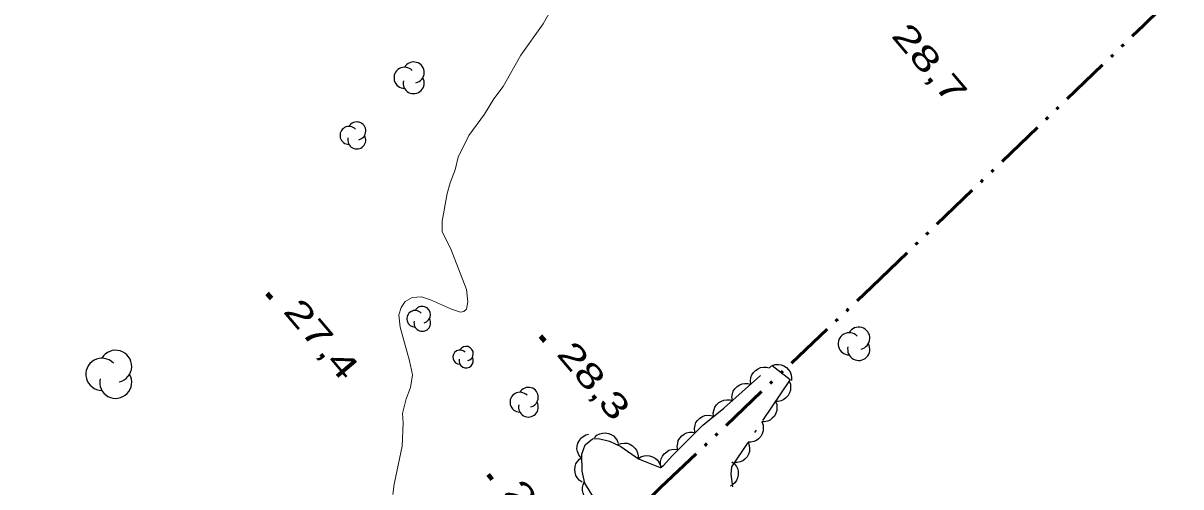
# Model space of a CAD drawing. Extents: x 386081 to 389416, y 5130568 to 5134082.
# Drawn here: x 388446.7 to 388588.2, y 5131862.1 to 5131918.7 of the extents above; entities that cross this region are included whole.
import ezdxf

# ---------------------------------------------------------------- set-up
doc = ezdxf.new("R2010")
doc.units = 0
doc.header["$LTSCALE"] = 1.2
doc.linetypes.add('DASH_DOUBLE_DOT', pattern=[9.2, 5, -1.2, 0.3, -1.2, 0.3, -1.2])
doc.linetypes.add('DOT_DASHED', pattern=[7.7, 5, -1.2, 0.3, -1.2])
for name, color, linetype, lineweight in [('2', 7, 'Continuous', 13), ('3', 7, 'Continuous', 140), ('4', 7, 'DASH_DOUBLE_DOT', 53), ('44', 7, 'Continuous', 25)]:
    doc.layers.add(name, color=color, linetype=linetype, lineweight=lineweight)

msp = doc.modelspace()

# ---------------------------------------------------------------- linework, layer by layer
at = {"layer": '2'}
msp.add_lwpolyline([(388491.9, 5131861.11), (388492.06, 5131862.38), (388493.02, 5131867.01), (388493.16, 5131869.86), (388493.06, 5131871), (388493.5, 5131872.79), (388494.05, 5131874.18), (388494.29, 5131875.74), (388493.93, 5131877.43), (388492.79, 5131881.57), (388492.61, 5131883.08), (388492.91, 5131883.98), (388493.4, 5131884.7), (388494.24, 5131885.19), (388495.39, 5131885.25), (388496.47, 5131884.89), (388499.06, 5131883.75), (388500.15, 5131883.4), (388500.57, 5131883.46), (388500.87, 5131883.76), (388501.05, 5131884.66), (388500.87, 5131886.17), (388498.95, 5131891.21), (388497.93, 5131893.2), (388497.93, 5131894.52), (388498.53, 5131897.89), (388498.9, 5131899.21), (388499.5, 5131900.78), (388499.87, 5131902.35), (388501.19, 5131904.99), (388503.07, 5131907.59), (388504.21, 5131909.45), (388505.36, 5131910.96), (388507.54, 5131914.81), (388510.25, 5131918.61), (388511.7, 5131921.14)], dxfattribs=at)
at = {"layer": '3'}
for p, q in [((388476.55, 5131885.68), (388477.06, 5131885.07)), ((388509.95, 5131880.45), (388510.46, 5131879.84)), ((388503.53, 5131863.57), (388504.04, 5131862.96))]:
    msp.add_line(p, q, dxfattribs=at)
at = {"layer": '4'}
msp.add_lwpolyline([(388403.08, 5131676.15), (388398.8, 5131683.5), (388385.24, 5131705.68), (388376.19, 5131718.23), (388378.12, 5131720.75), (388380.58, 5131723.47), (388405.01, 5131746.47), (388448.58, 5131788.82), (388515.07, 5131852.58), (388524.6, 5131861.96), (388550.41, 5131886.49), (388583.66, 5131918.46), (388613.94, 5131948.36), (388649.63, 5131983.32), (388677.59, 5132010.13), (388707.98, 5132038.7), (388732.5, 5132062.17)], dxfattribs=at)
at = {"layer": '44', "linetype": 'DOT_DASHED'}
msp.add_lwpolyline([(388517.16, 5131859.62), (388515.36, 5131862.51), (388515.01, 5131863.95), (388514.99, 5131866.03), (388515.37, 5131867.18), (388516.27, 5131867.91), (388517, 5131867.95), (388518.37, 5131867.63), (388519.74, 5131866.97), (388521.92, 5131865.46), (388524.54, 5131864.4), (388524.98, 5131864.67), (388526.03, 5131865.86), (388529.77, 5131869.59), (388532.32, 5131871.68), (388538.22, 5131876.87), (388540.42, 5131875.16), (388533.27, 5131864.5), (388533.2, 5131863.59), (388533.38, 5131862.04)], dxfattribs=at)
at = {"layer": '44'}
for points in [[(388535.63, 5131874.59), (388535.58, 5131875.01), (388535.65, 5131875.41), (388535.75, 5131875.73), (388535.94, 5131876.02), (388536.2, 5131876.28), (388536.52, 5131876.49), (388536.82, 5131876.63), (388537.17, 5131876.68), (388537.54, 5131876.67), (388537.89, 5131876.58)], [(388538.22, 5131876.87), (388538.62, 5131877), (388539.02, 5131877.01), (388539.35, 5131876.97), (388539.68, 5131876.83), (388539.99, 5131876.63), (388540.24, 5131876.35), (388540.44, 5131876.09), (388540.55, 5131875.75), (388540.61, 5131875.39), (388540.59, 5131875.03)], [(388533.38, 5131872.61), (388533.33, 5131873.03), (388533.4, 5131873.43), (388533.49, 5131873.74), (388533.69, 5131874.04), (388533.95, 5131874.3), (388534.27, 5131874.5), (388534.57, 5131874.65), (388534.91, 5131874.69), (388535.28, 5131874.68), (388535.63, 5131874.59)], [(388540.3, 5131874.98), (388540.46, 5131874.6), (388540.49, 5131874.19), (388540.48, 5131873.86), (388540.37, 5131873.53), (388540.19, 5131873.2), (388539.92, 5131872.93), (388539.68, 5131872.71), (388539.35, 5131872.58), (388538.99, 5131872.49), (388538.63, 5131872.49)], [(388531.09, 5131870.67), (388531.05, 5131871.09), (388531.14, 5131871.49), (388531.25, 5131871.8), (388531.45, 5131872.08), (388531.72, 5131872.34), (388532.05, 5131872.53), (388532.35, 5131872.66), (388532.7, 5131872.7), (388533.07, 5131872.68), (388533.41, 5131872.58)], [(388538.63, 5131872.49), (388538.79, 5131872.1), (388538.82, 5131871.7), (388538.81, 5131871.37), (388538.69, 5131871.04), (388538.52, 5131870.71), (388538.25, 5131870.43), (388538, 5131870.22), (388537.68, 5131870.09), (388537.32, 5131870), (388536.96, 5131870)], [(388528.77, 5131868.77), (388528.73, 5131869.19), (388528.82, 5131869.59), (388528.92, 5131869.9), (388529.13, 5131870.18), (388529.4, 5131870.44), (388529.73, 5131870.63), (388530.03, 5131870.76), (388530.38, 5131870.8), (388530.75, 5131870.78), (388531.09, 5131870.67)], [(388536.96, 5131870), (388537.12, 5131869.61), (388537.15, 5131869.21), (388537.14, 5131868.88), (388537.02, 5131868.55), (388536.85, 5131868.22), (388536.58, 5131867.94), (388536.33, 5131867.73), (388536.01, 5131867.6), (388535.65, 5131867.51), (388535.29, 5131867.51)], [(388514.87, 5131865.65), (388514.61, 5131865.98), (388514.47, 5131866.36), (388514.39, 5131866.68), (388514.41, 5131867.04), (388514.5, 5131867.4), (388514.68, 5131867.73), (388514.86, 5131868), (388515.14, 5131868.22), (388515.46, 5131868.4), (388515.81, 5131868.5)], [(388516.51, 5131868.06), (388516.82, 5131868.35), (388517.19, 5131868.52), (388517.5, 5131868.63), (388517.85, 5131868.64), (388518.22, 5131868.59), (388518.57, 5131868.44), (388518.86, 5131868.28), (388519.1, 5131868.02), (388519.31, 5131867.72), (388519.44, 5131867.38)], [(388519.39, 5131867.21), (388519.78, 5131867.36), (388520.18, 5131867.39), (388520.51, 5131867.38), (388520.84, 5131867.26), (388521.17, 5131867.07), (388521.44, 5131866.8), (388521.65, 5131866.55), (388521.78, 5131866.23), (388521.86, 5131865.86), (388521.86, 5131865.5)], [(388526.73, 5131866.56), (388526.65, 5131866.97), (388526.7, 5131867.37), (388526.77, 5131867.7), (388526.95, 5131868), (388527.19, 5131868.28), (388527.5, 5131868.5), (388527.79, 5131868.66), (388528.13, 5131868.73), (388528.5, 5131868.75), (388528.86, 5131868.68)], [(388535.29, 5131867.51), (388535.44, 5131867.12), (388535.48, 5131866.72), (388535.47, 5131866.39), (388535.35, 5131866.05), (388535.17, 5131865.73), (388534.91, 5131865.45), (388534.66, 5131865.24), (388534.34, 5131865.1), (388533.98, 5131865.02), (388533.62, 5131865.02)], [(388524.7, 5131864.35), (388524.6, 5131864.76), (388524.61, 5131865.16), (388524.67, 5131865.49), (388524.83, 5131865.8), (388525.05, 5131866.1), (388525.35, 5131866.34), (388525.62, 5131866.52), (388525.96, 5131866.61), (388526.33, 5131866.65), (388526.69, 5131866.6)], [(388515.02, 5131862.63), (388514.67, 5131862.86), (388514.42, 5131863.18), (388514.24, 5131863.46), (388514.15, 5131863.8), (388514.11, 5131864.16), (388514.17, 5131864.54), (388514.26, 5131864.86), (388514.45, 5131865.15), (388514.7, 5131865.43), (388514.99, 5131865.63)], [(388521.85, 5131865.49), (388522.19, 5131865.72), (388522.58, 5131865.84), (388522.91, 5131865.89), (388523.26, 5131865.85), (388523.61, 5131865.74), (388523.94, 5131865.54), (388524.2, 5131865.34), (388524.39, 5131865.05), (388524.55, 5131864.72), (388524.63, 5131864.36)], [(388533.32, 5131865.12), (388533.64, 5131864.86), (388533.88, 5131864.53), (388534.03, 5131864.23), (388534.09, 5131863.89), (388534.09, 5131863.52), (388534, 5131863.14), (388533.89, 5131862.84), (388533.67, 5131862.56), (388533.4, 5131862.31), (388533.09, 5131862.13)], [(388516.86, 5131860.1), (388516.44, 5131860.12), (388516.06, 5131860.25), (388515.76, 5131860.4), (388515.51, 5131860.64), (388515.28, 5131860.94), (388515.14, 5131861.29), (388515.05, 5131861.6), (388515.06, 5131861.96), (388515.13, 5131862.32), (388515.27, 5131862.65)]]:
    msp.add_lwpolyline(points, dxfattribs=at)
for centre, radius, start, end in [((388493.319, 5131912.029), 1.292, 44.11537, 269.80396), ((388493.319, 5131912.029), 1.292, 44.11537, 269.80396), ((388494.43, 5131912.675), 1.292, 282.26917, 149.72626), ((388494.43, 5131912.675), 1.292, 282.26917, 149.72626), ((388494.43, 5131911.383), 1.292, 166.93686, 29.62122), ((388494.43, 5131911.383), 1.292, 166.93686, 29.62122), ((388486.533, 5131904.985), 1.1, 44.11537, 269.80396), ((388487.479, 5131905.535), 1.1, 282.26917, 149.72626), ((388487.479, 5131904.435), 1.1, 166.93686, 29.62122), ((388494.612, 5131882.583), 1.014, 44.11537, 269.80396), ((388495.483, 5131883.09), 1.014, 282.26917, 149.72626), ((388495.483, 5131882.076), 1.014, 166.93686, 29.62122), ((388548.817, 5131880.21), 1.357, 282.26917, 149.72626), ((388547.65, 5131879.531), 1.357, 44.11537, 269.80396), ((388458.018, 5131876.784), 1.959, 282.26917, 149.72626), ((388500.092, 5131877.9), 0.877, 44.11537, 269.80396), ((388500.846, 5131878.339), 0.877, 282.26917, 149.72626), ((388548.817, 5131878.852), 1.357, 166.93686, 29.62122), ((388456.333, 5131875.804), 1.959, 44.11537, 269.80396), ((388500.846, 5131877.461), 0.877, 166.93686, 29.62122), ((388458.018, 5131874.825), 1.959, 166.93686, 29.62122), ((388507.415, 5131872.397), 1.21, 44.11537, 269.80396), ((388508.455, 5131873.003), 1.21, 282.26917, 149.72626), ((388508.455, 5131871.792), 1.21, 166.93686, 29.62122)]:
    msp.add_arc(centre, radius, start, end, dxfattribs=at)

# ---------------------------------------------------------------- texts
at = {"layer": '3'}
for s, width, p in [('28,7   ', 1.45, (388552.69, 5131917.13)), ('27,4   ', 1.45, (388478.38, 5131883.46)), ('28,3   ', 1.4, (388511.78, 5131878.23)), ('28,2   ', 1.45, (388505.36, 5131861.35))]:
    msp.add_text(s, height=3, rotation=310.294, dxfattribs=dict(at, width=width)).set_placement(p)

doc.saveas('drawing.dxf')
